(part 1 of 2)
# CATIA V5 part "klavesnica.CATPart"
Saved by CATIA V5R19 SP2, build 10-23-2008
Part number: Part1
Bounding box of the stored display mesh (mm): x -64 to 64, y -20 to 20, z 0 to 7.5
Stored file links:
  D:\Škola\Catia\Ovladac\klavesnica.CATPart
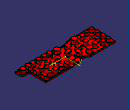
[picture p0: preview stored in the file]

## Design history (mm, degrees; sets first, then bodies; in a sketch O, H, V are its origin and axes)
Body1 (main body)
  Sketch1 on xy-plane, origin (0, 0, 0), H (1, 0, 0), V (0, 1, 0)
    line L1 (-64, -20) -> (64, -20)
    point P2 (64, -20)
    line L2 (-64, -20) -> (-64, 20)
    point P3 (-64, 20)
    line L3 (64, -20) -> (64, -7)
    line L4 (-64, 20) -> (52, 20)
    line L5 (52, 20) -> (52, -7)
    line L6 (64, -7) -> (52, -7)
    length L1 = 128
    distance P2 V = 64
    length L2 = 40
    distance P3 H = 20
    length L3 = 13
    length L4 = 116
    horizontal: L1 H, L4 H, L6 H
    vertical: L2 V, L3 V, L5 V
  Pad1: profile Sketch1, direction (0, 0, 1), length 1
  Sketch2 on end face of Pad1, origin (0, 0, 1), H (1, 0, 0), V (0, 1, 0)
    line L1 (-64, -20) -> (61, -20)
    point P2 (64, -20)
    line L2 (64, -17) -> (64, -12)
    point P3 (64, -7)
    line L3 (59, -7) -> (52, -7)
    line L4 (52, -7) -> (52, 20)
    line L5 (52, 20) -> (-64, 20)
    line L6 (-64, 20) -> (-64, -20)
    line L7 (-63, 19) -> (51, 19)
    line L8 (-63, 19) -> (-63, -19)
    line L9 (-63, -19) -> (60, -19)
    line L10 (63, -16) -> (63, -13)
    line L11 (58, -8) -> (51, -8)
    line L12 (51, -8) -> (51, 19)
    arc A1 centre (58, -13) radius 5 from (63, -13) to (58, -8) ccw
    arc A2 centre (59, -12) radius 5 from (64, -12) to (59, -7) ccw
    reference projected line E1 (64, -20) -> (64, -7) from edge [face of Pad1 from Sketch1.L3 | end face of Pad1]
    arc A3 centre (60, -16) radius 3 from (63, -16) to (60, -19) cw
    arc A4 centre (61, -17) radius 3 from (64, -17) to (61, -20) cw
    reference projected line E2 (52, -7) -> (52, 20) from edge [face of Pad1 from Sketch1.L5 | end face of Pad1]
    distance L7 L5 = 1
    distance L9 L1 = 1
    distance L8 L6 = 1
    distance L11 L3 = 1
    radius A1 = 5
    radius A2 = 5
    distance L10 E1 = 1
    radius A3 = 3
    radius A4 = 3
    distance E2 L4 = 0
    distance L4 L12 = 1
    horizontal: L1 H, L3 H, L5 H, L7 H, L9 H, L11 H
    vertical: L2 V, L4 V, L6 V, L8 V, L10 V, L12 V
    tangency: A1 L10, A1 L11, A2 L2, A2 L3, A3 L10, A3 L9, A4 L2, A4 L1
    coincidence: L2 P3, L3 P3, L2 P2
  Pad2: profile Sketch2, direction (0, 0, 1), length 1
  Sketch3 on end face of Pad2, origin (0, 0, 2), H (1, 0, 0), V (0, 1, 0)
    line L1 (-68, 9) -> (-58, 9)
    line L2 (-58, 9) -> (-58, 19)
    line L3 (-58, 19) -> (-68, 19)
    line L4 (-68, 19) -> (-68, 9)
    reference projected line E1 (52, 20) -> (-64, 20) from edge [face of Pad2 | end face of Pad2]
    length L4 = 10
    distance L3 E1 = 1
    horizontal: L1 H, L3 H
    vertical: L2 V, L4 V
  Pocket1: profile Sketch3, direction (0, 0, -1), length 1
  Sketch4 on end face of Pad2, origin (0, 0, 2), H (1, 0, 0), V (0, 1, 0)
    circle A1 centre (-64, 0) radius 2.5
    point P1 (-64, 0)
    reference projected line E1 (-64, 9) -> (-63, 9) from edge [end face of Pad2 | face of Pocket1 from Sketch3.L1]
    reference projected line E2 (-64, 20) -> (-64, -20) from edge [face of Pad2 | end face of Pad2]
    radius A1 = 2.5
    distance P1 E1 = 9
    distance P1 E2 = 0
  Pocket2: profile Sketch4, direction (0, 0, -1), length 3
  Sketch5 on face of Pocket1, origin (0, 0, 1), H (1, 0, 0), V (0, 1, 0)
    arc A1 centre (-64, 0) radius 2 from (-64, -2) to (-64, 2) ccw
    point P1 (-64, 0)
    arc A2 centre (-64, 0) radius 2.5 from (-64, -2.5) to (-64, 2.5) ccw
    line L1 (-64, -2) -> (-64, -2.5)
    line L2 (-64, 2) -> (-64, 2.5)
    radius A1 = 2
    radius A2 = 2.5
    coincidence: P1 H
    vertical: L1 V, L2 V
  Pad3: profile Sketch5, direction (0, 0, 1), length 1
  Sketch6 on face of Pad3, origin (0, 0, 2), H (1, 0, 0), V (0, 1, 0)
    line L1 (-22, -20) -> (-18.5, -16.8182)
    point P1 (-22, -20)
    point P2 (-18.5, -16.8182)
    line L2 (-22, -20) -> (-5, -20)
    point P3 (-5, -20)
    line L3 (-5, -20) -> (-8.5, -16.8182)
    point P4 (-8.5, -16.8182)
    axis line L4 (-13.5, -22) -> (-13.5, -10)
    line L5 (-8.5, -16.8182) -> (-18.5, -16.8182)
    point P7 (-5, 20)
    point P8 (-22, 20)
    line L6 (-22, 20) -> (-5, 20)
    point P9 (-8.5, 16.8182)
    line L7 (-5, 20) -> (-8.5, 16.8182)
    point P10 (-18.5, 16.8182)
    line L8 (-8.5, 16.8182) -> (-18.5, 16.8182)
    line L9 (-22, 20) -> (-18.5, 16.8182)
    length L2 = 17
    distance P3 V = 5
    distance L4 P1 = 8.5
    coincidence: L1 O
    horizontal: L2 H, L5 H
    vertical: L4 V
    symmetry: P3 P7 H, P1 P8 H, L2 L6 H, P4 P9 H, L3 L7 H, P2 P10 H, L5 L8 H, L1 L9 H
  Pocket3: profile Sketch6, direction (0, 0, -1), length 4
  Sketch7 on face of Pad2, origin (0, 20, 0), H (-1, 0, 0), V (0, 0, 1)
    reference projected line E1 (-52, 0) -> (64, 0) from edge [start face of Pad1 | face of Pad2]
    reference projected line E2 (-52, 2) -> (64, 2) from edge [face of Pad2 | face of Pad3]
    distance E1 E2 = 2 (reference)
  Sketch8 on face of Pocket1, origin (0, 0, 1), H (1, 0, 0), V (0, 1, 0)
    point P1 (-6, -20)
    line L1 (-6, -20) -> (4, -20)
    line L2 (4, -20) -> (4, -19)
    line L3 (4, -19) -> (-6, -19)
    line L4 (-6, -19) -> (-6, -20)
    point P2 (4, -20)
    point P3 (4, -19)
    point P4 (-6, -19)
    reference projected point E1 (-5, -20) from vertex [face of Pocket3 from Sketch6.L3 | face of Pad2 | face of Pad3]
    point P5 (-6, 19)
    point P6 (4, 19)
    line L5 (4, 19) -> (-6, 19)
    point P7 (-6, 20)
    line L6 (-6, 19) -> (-6, 20)
    point P8 (4, 20)
    line L7 (-6, 20) -> (4, 20)
    line L8 (4, 20) -> (4, 19)
    length L1 = 10
    distance L4 E1 = 1
    length L4 = 1
    horizontal: L1 H, L3 H
    vertical: L2 V, L4 V
    symmetry: P4 P5 H, P3 P6 H, L3 L5 H, P1 P7 H, L4 L6 H, P2 P8 H, L1 L7 H, L2 L8 H
  Pocket4: profile Sketch8, direction (0, 0, 1), length 3, mirrored extent
  Sketch9 on face of Pad3, origin (0, 0, 2), H (1, 0, 0), V (0, 1, 0)
    point P1 (-6, -19)
    line L1 (-6, -19) -> (-10, -19)
    line L2 (-10, -19) -> (-10, -21)
    line L3 (-10, -21) -> (-6, -21)
    line L4 (-6, -21) -> (-6, -19)
    point P2 (-10, -19)
    point P3 (-10, -21)
    point P4 (-6, -21)
    reference projected line E1 (-63, -19) -> (63, -19) from edge [face of Pad3 | face of Pad2 from Sketch2.L9]
    point P5 (-6, 19)
    point P6 (-6, 21)
    line L5 (-6, 21) -> (-6, 19)
    point P7 (-10, 19)
    line L6 (-6, 19) -> (-10, 19)
    point P8 (-10, 21)
    line L7 (-10, 21) -> (-6, 21)
    line L8 (-10, 19) -> (-10, 21)
    distance E1 L1 = 0
    horizontal: L1 H, L3 H
    vertical: L2 V, L4 V
    symmetry: P1 P5 H, P4 P6 H, L4 L5 H, P2 P7 H, L1 L6 H, P3 P8 H, L3 L7 H, L2 L8 H
  Pocket5: profile Sketch9, direction (0, 0, -1), length 3
  Sketch10 on face of Pocket1, origin (0, 0, 1), H (1, 0, 0), V (0, 1, 0)
    line L1 (-18.5, -16.8182) -> (-8.5, -16.8182)
    point P1 (-18.5, -16.8182)
    point P2 (-8.5, -16.8182)
    line L2 (-18.5, -16.8182) -> (-22.0601, -20.0546)
    point P3 (-22.0601, -20.0546)
    line L3 (-22.0601, -20.0546) -> (-22.0601, -20.0546)
    line L4 (-22.0601, -20.0546) -> (-22.7466, -19.3275)
    point P5 (-22.7466, -19.3275)
    line L5 (-22.7466, -19.3275) -> (-18.8863, -15.8182)
    line L6 (-18.8863, -15.8182) -> (-8.1151, -15.8182)
    point P6 (-18.8863, -15.8182)
    point P7 (-6.1, -19)
    line L7 (-6.1, -19) -> (4, -19)
    point P8 (4, -19)
    line L8 (4, -19) -> (4, -18)
    point P9 (4, -18)
    line L9 (4, -18) -> (-5.7151, -18)
    line L10 (-6.1, -19) -> (-8.5, -16.8182)
    line L11 (-5.7151, -18) -> (-8.1151, -15.8182)
    point P10 (-5.7151, -18)
    point P11 (-8.1151, -15.8182)
    point P12 (-8.1151, 15.8182)
    point P13 (-18.8863, 15.8182)
    line L12 (-18.8863, 15.8182) -> (-8.1151, 15.8182)
    point P14 (-8.5, 16.8182)
    point P15 (-18.5, 16.8182)
    line L13 (-18.5, 16.8182) -> (-8.5, 16.8182)
    point P16 (-22.0601, 20.0546)
    line L14 (-18.5, 16.8182) -> (-22.0601, 20.0546)
    point P17 (-22.7466, 19.3275)
    line L15 (-22.7466, 19.3275) -> (-18.8863, 15.8182)
    line L16 (-22.0601, 20.0546) -> (-22.7466, 19.3275)
    point P18 (-5.7151, 18)
    line L17 (-5.7151, 18) -> (-8.1151, 15.8182)
    point P19 (-6.1, 19)
    line L18 (-6.1, 19) -> (-8.5, 16.8182)
    point P20 (4, 18)
    line L19 (4, 18) -> (-5.7151, 18)
    point P21 (4, 19)
    line L20 (-6.1, 19) -> (4, 19)
    line L21 (4, 19) -> (4, 18)
    symmetry: P11 P12 H, P6 P13 H, L6 L12 H, P2 P14 H, P1 P15 H, L1 L13 H, P3 P16 H, L2 L14 H, P5 P17 H, L5 L15 H, L4 L16 H, P10 P18 H, L11 L17 H, P7 P19 H, L10 L18 H, P9 P20 H, L9 L19 H, P8 P21 H, L7 L20 H, L8 L21 H
  Sketch11 on face of Pocket1, origin (0, 0, 1), H (1, 0, 0), V (0, 1, 0)
    line L1 (4, -19) -> (4, -18)
    point P1 (4, -19)
    reference projected point E1 (4, -19) from vertex [element of Sketch10 | element of Sketch10]
    length L1 = 1
    distance P1 E1 = 0
    vertical: L1 V
  Pad4: profile Sketch10, direction (0, 0, 1), length 1
  Sketch12 on face of Pad4, origin (0, 0, 2), H (1, 0, 0), V (0, 1, 0)
    line L1 (10, -20) -> (6, -20)
    point P1 (10, -20)
    point P2 (6, -20)
    line L2 (10, -20) -> (10, -19)
    point P3 (10, -19)
    line L3 (10, -19) -> (6, -19)
    point P4 (6, -19)
    line L4 (6, -20) -> (4, -19)
    point P5 (4, -19)
    line L5 (4, -18) -> (6, -19)
    point P6 (4, -18)
    line L6 (4, -18) -> (4, -19)
    point P7 (6, 19)
    point P8 (4, 18)
    line L7 (4, 18) -> (6, 19)
    point P9 (4, 19)
    point P10 (6, 20)
    line L8 (6, 20) -> (4, 19)
    line L9 (4, 18) -> (4, 19)
    point P11 (10, 19)
    line L10 (10, 19) -> (6, 19)
    point P12 (10, 20)
    line L11 (10, 20) -> (10, 19)
    line L12 (10, 20) -> (6, 20)
    length L1 = 4
    length L2 = 1
    horizontal: L1 H, L3 H
    vertical: L2 V
    coincidence: P5 L3
    parallelism: L4 L5, L6 L2
    symmetry: P4 P7 H, P6 P8 H, L5 L7 H, P5 P9 H, P2 P10 H, L4 L8 H, L6 L9 H, P3 P11 H, L3 L10 H, P1 P12 H, L2 L11 H, L1 L12 H
  Pocket6: profile Sketch12, direction (0, 0, -1), length 1
  Sketch13 on face of Pad3, origin (0, 0, 2), H (1, 0, 0), V (0, 1, 0)
    point P1 (4, -19)
    line L1 (4, -19) -> (4, -20)
    point P2 (4, -20)
    line L2 (4, -20) -> (6, -20)
    point P3 (6, -20)
    line L3 (6, -20) -> (4, -19)
    point P4 (4, 19)
    point P5 (6, 20)
    line L4 (6, 20) -> (4, 19)
    point P6 (4, 20)
    line L5 (4, 20) -> (6, 20)
    line L6 (4, 19) -> (4, 20)
    vertical: L1 V
    horizontal: L2 H
    symmetry: P1 P4 H, P3 P5 H, L3 L4 H, P2 P6 H, L2 L5 H
  Pocket7: profile Sketch13, direction (0, 0, -1), length 3
  Sketch14 on end face of Pad1, origin (0, 0, 1), H (1, 0, 0), V (0, 1, 0)
    line L1 (64, -12) -> (64, -14.0135)
    line L2 (59, -7) -> (56, -7)
    arc A1 centre (59, -12) radius 5 from (64, -12) to (59, -7) ccw
    line L3 (64, -14.0135) -> (68, -14.0135)
    line L4 (68, -14.0135) -> (68, -6)
    line L5 (68, -6) -> (56, -6)
    line L6 (56, -6) -> (56, -7)
    radius A1 = 5
    vertical: L1 V, L4 V, L6 V
    horizontal: L2 H, L3 H, L5 H
    tangency: A1 L1, A1 L2
  Pocket8: profile Sketch14, direction (0, 0, -1), length 3
  Sketch15 on end face of Pad1, origin (0, 0, 1), H (1, 0, 0), V (0, 1, 0)
    line L1 (64, -17) -> (64, -14.8164)
    line L2 (61, -20) -> (56.8164, -20)
    arc A1 centre (61, -17) radius 3 from (61, -20) to (64, -17) ccw
    reference projected line E1 (64, -17) -> (64, -12) from edge [face of Pocket8 | face of Pad3]
    line L3 (56.8164, -20) -> (56.8164, -22)
    line L4 (56.8164, -22) -> (66, -22)
    line L5 (66, -22) -> (66, -14.8164)
    line L6 (66, -14.8164) -> (64, -14.8164)
    radius A1 = 3
    distance L1 E1 = 0
    vertical: L1 V, L3 V, L5 V
    horizontal: L2 H, L4 H, L6 H
    tangency: A1 L2, A1 L1
  Pocket9: profile Sketch15, direction (0, 0, -1), length 3
  Sketch16 on face of Pocket6, origin (0, 0, 1), H (1, 0, 0), V (0, 1, 0)
    line L1 (69.438, -27) -> (57.438, -27)
    line L2 (57.438, -27) -> (57.438, -20)
    line L3 (58.438, -19) -> (69.438, -19)
    line L4 (69.438, -19) -> (69.438, -27)
    reference projected line E1 (-64, -20) -> (61, -20) from edge [face of Pocket9 | face of Pad3]
    reference projected line E2 (64, -17) -> (64, -12) from edge [face of Pocket9 | face of Pad3]
    arc A1 centre (58.438, -20) radius 1 from (58.438, -19) to (57.438, -20) ccw
    distance L3 E1 = 1
    distance E2 L2 = 6.562
    radius A1 = 1
    horizontal: L1 H, L3 H
    vertical: L2 V, L4 V
    tangency: A1 L3, A1 L2
  Pocket10: profile Sketch16, direction (0, 0, -1), length 3, mirrored extent
  Sketch17 on face of Pocket6, origin (0, 0, 1), H (1, 0, 0), V (0, 1, 0)
    point P1 (60, -19)
    point P2 (57.438, -18)
    arc A1 centre (58.438, -20) radius 1 from (58.438, -19) to (57.438, -20) ccw
    point P4 (57.438, -20)
    line L1 (57.438, -20) -> (57.438, -19)
    arc A2 centre (58.438, -19) radius 1 from (58.438, -18) to (57.438, -19) ccw
    reference projected point E1 (60, -19) from vertex [face of Pad2 from Sketch2.A3 | face of Pocket10 from Sketch16.L3 | face of Pad3]
    line L2 (58.438, -19) -> (62.088, -19)
    line L3 (58.438, -18) -> (62.088, -18)
    line L4 (62.088, -18) -> (62.088, -19)
    reference projected arc E2 centre (58.438, -20) radius 1 from (58.438, -19) to (57.438, -20) ccw from edge [face of Pad3 | face of Pocket10 from Sketch16.A1]
    distance P4 P2 = 2
    radius A2 = 1
    distance P1 E1 = 0
    distance P4 E2 = 0
    vertical: L1 V
    coincidence: L1 P2
    tangency: A2 L1, L2 A1, L3 A2
    parallelism: L4 L1
  Pad5: profile Sketch17, direction (0, 0, 1), length 1
  Sketch18 on face of Pocket6, origin (0, 0, 1), H (1, 0, 0), V (0, 1, 0)
    circle A1 centre (-58, -13.8) radius 3
    reference projected line E1 (-64, -20) -> (61, -20) from edge [face of Pad2 | face of Pad4]
    circle A2 centre (-58, -4.6) radius 3
    circle A3 centre (-58, 4.6) radius 3
    circle A4 centre (-58, 13.8) radius 3
    reference projected line E2 (52, 20) -> (-64, 20) from edge [face of Pad2 | face of Pad4]
    reference projected line E3 (-64, 19) -> (-64, 9) from edge [face of Pad2 | face of Pocket1]
    reference projected line E4 (-64, 20) -> (-64, -20) from edge [face of Pad3 | face of Pad4]
    reference projected line E5 (-64, -2) -> (-64, -20) from edge [face of Pad3 | face of Pad3]
    reference projected line E8 (-64, -2) -> (-64, -20) from edge [face of Pad3 | face of Pad3]
    axis line L1 (-53.5, -30) -> (-53.5, 28)
    circle A5 centre (-49, 13.8) radius 3
    circle A6 centre (-49, 4.6) radius 3
    circle A7 centre (-49, -4.6) radius 3
    circle A8 centre (-49, -13.8) radius 3
    radius A1 = 3
    distance E1 A1 = 3.2
    radius A2 = 3
    radius A4 = 3
    distance A4 E2 = 3.2
    distance A4 A3 = 3.2
    radius A3 = 3
    distance A4 E3 = 3
    distance A3 E4 = 3
    distance A1 E5 = 3
    distance A2 A1 = 3.2
    distance A2 E8 = 3
    distance L1 A4 = 1.5
    vertical: L1 V
    symmetry: A4 A5 L1, A3 A6 L1, A2 A7 L1, A1 A8 L1
  Pad6: profile Sketch18, direction (0, 0, 1), length 0.5
  Draft1: PullDir end face of Pad6, Angle 33, SupportToDraft face of Pad6 from Sketch18.A1, Neutral end face of Pad6, deactivated
  Pad7: profile Sketch18, direction (0, 0, 1), length 0.5
  Draft2: PullDir end face of Pad6, Angle 30, SupportToDraft face of Pad7, Neutral face of Pad7, deactivated
  Draft3: PullDir end face of Pad6, Angle 33, SupportToDraft face of Pad7, Neutral face of Pad7, deactivated
  Draft4: PullDir end face of Pad6, Angle 33, SupportToDraft face of Pad7, Neutral face of Pad7, deactivated
  Draft5: PullDir end face of Pad6, Angle 33, SupportToDraft face of Pad7, Neutral face of Pad7, deactivated
  Draft6: PullDir end face of Pad6, Angle 33, SupportToDraft face of Pad7, Neutral face of Pad7, deactivated
  Draft7: PullDir end face of Pad6, Angle 33, SupportToDraft face of Pad7, Neutral face of Pad7, deactivated
  Sketch19 on face of Pocket6, origin (0, 0, 1), H (1, 0, 0), V (0, 1, 0)
    circle A1 centre (-39.2169, -10.5) radius 3.5
    reference projected line E1 (-63, -19) -> (60, -19) from edge [face of Pad4 | face of Pad2 from Sketch2.L9]
    reference projected circle E2 centre (-49, -13.8) radius 3.3247 from edge [face of Pad7 | face of Pocket6]
    circle A2 centre (-39.2169, 10.5) radius 3.5
    distance A1 E1 = 5
    radius A1 = 3.5
    distance A1 E2 = 3.5
    symmetry: A1 A2 H
  Pad8: profile Sketch19, direction (0, 0, 1), length 0.5, deactivated
  Draft8: PullDir end face of Pad6, Angle 33, SupportToDraft face of Pad8 from Sketch19.A1, Neutral end face of Pad8, deactivated
  Draft9: PullDir end face of Pad6, Angle 33, SupportToDraft face of Pad8, Neutral end face of Pad8, deactivated
  Sketch20 on face of Pocket6, origin (0, 0, 1), H (1, 0, 0), V (0, 1, 0)
    circle A1 centre (-27.8728, -12.5) radius 4.5
    reference projected line E1 (-64, -20) -> (61, -20) from edge [face of Pad2 | face of Pad4]
    reference projected line E2 (-18.5, -16.8182) -> (-22.0601, -20.0546) from edge [face of Pad4 | face of Pad4]
    circle A2 centre (-27.8728, 12.5) radius 4.5
    circle A3 centre (0.8728, -12.5) radius 4.5
    circle A4 centre (0.8728, 12.5) radius 4.5
    radius A1 = 4.5
    distance A1 E1 = 3
    distance E2 A1 = 5
    symmetry: A1 A2 H
  Pad9: profile Sketch20, direction (0, 0, 1), length 0.5
  Draft10: PullDir end face of Pad6, Angle 33, SupportToDraft face of Pad9, Neutral end face of Pad9, deactivated
  Draft11: PullDir end face of Pad6, Angle 33, SupportToDraft face of Pad9 from Sketch20.A1, Neutral end face of Pad9, deactivated
  Sketch21 on face of Pocket6, origin (0, 0, 1), H (1, 0, 0), V (0, 1, 0)
    circle A1 centre (-34, 0) radius 3.25
    point P1 (-34, 0)
    radius A1 = 3.25
    distance V P1 = 34
    coincidence: P1 H
  Pad10: profile Sketch21, direction (0, 0, 1), length 0.5
  Draft12: PullDir end face of Pad6, Angle 33, SupportToDraft face of Pad10 from Sketch21.A1, Neutral end face of Pad10, deactivated
  Sketch22 on start face of Pad4, origin (0, 0, 1), H (1, 0, 0), V (0, -1, 0)
    line L1 (-22, 20) -> (-26, 20)
    line L2 (-26, 20) -> (-26, 22)
    line L3 (-26, 22) -> (-22, 22)
    line L4 (-22, 22) -> (-22, 20)
    horizontal: L1 H, L3 H
    vertical: L2 V, L4 V
  Pocket11: profile Sketch22, direction (0, 0, 1), length 1.5
  Sketch23 on start face of Pad4, origin (0, 0, 1), H (1, 0, 0), V (0, -1, 0)
    line L1 (-20, -20) -> (-24, -20)
    line L2 (-24, -20) -> (-24, -22)
    line L3 (-24, -22) -> (-20, -22)
    line L4 (-20, -22) -> (-20, -20)
    horizontal: L1 H, L3 H
    vertical: L2 V, L4 V
  Pocket12: profile Sketch23, direction (0, 0, 1), length 1.5
  Draft13: PullDir end face of Pad6, Angle 33, SupportToDraft face of Pad8 from Sketch19.A2, Neutral end face of Pad8, deactivated
  Draft14: PullDir end face of Pad6, Angle 33, SupportToDraft face of Pad9 from Sketch20.A2, Neutral end face of Pad9, deactivated
  Draft15: PullDir end face of Pad6, Angle 33, SupportToDraft face of Pad9 from Sketch20.A3, Neutral end face of Pad9, deactivated
  Draft16: PullDir end face of Pad6, Angle 33, SupportToDraft face of Pad9 from Sketch20.A4, Neutral end face of Pad9
  Sketch24 on face of Pocket6, origin (0, 0, 1), H (1, 0, 0), V (0, 1, 0)
    arc A1 centre (11.8207, -16) radius 2 from (10.3658, -17.3723) to (11.8207, -18) ccw
    arc A2 centre (11.8207, -12) radius 2 from (11.8207, -10) to (10.415, -10.5773) ccw
    arc A3 centre (13.9293, -14.134) radius 5 from (9.3483, -12.1304) to (10.415, -10.5773) cw
    point P1 (9.3483, -12.1304)
    point P2 (10.415, -10.5773)
    arc A4 centre (14.0031, -13.9416) radius 5 from (10.3658, -17.3723) to (9.2628, -12.351) cw
    point P3 (10.3658, -17.3723)
    point P4 (9.2628, -12.351)
    point P5 (11.8207, -10)
    point P6 (11.8207, -18)
    point P7 (13.2265, -10.5773)
    point P8 (11.8207, -10)
    arc A5 centre (11.8207, -12) radius 2 from (11.8207, -10) to (13.2265, -10.5773) cw
    point P9 (14.2932, -12.1304)
    arc A6 centre (9.7122, -14.134) radius 5 from (14.2932, -12.1304) to (13.2265, -10.5773) ccw
    point P10 (14.3786, -12.351)
    point P11 (13.2757, -17.3723)
    arc A7 centre (9.6384, -13.9416) radius 5 from (13.2757, -17.3723) to (14.3786, -12.351) ccw
    point P12 (11.8207, -18)
    arc A8 centre (11.8207, -16) radius 2 from (13.2757, -17.3723) to (11.8207, -18) cw
    line L1 (14.3786, -12.351) -> (14.2932, -12.1304)
    line L2 (9.2628, -12.351) -> (9.3483, -12.1304)
    reference projected line E1 (-64, -20) -> (61, -20) from edge [face of Pocket9 | face of Pad5]
    reference projected line E2 (-64, -20) -> (61, -20) from edge [face of Pocket9 | face of Pad5]
    point P13 (13.2265, 10.5773)
    point P14 (14.2932, 12.1304)
    arc A9 centre (9.7122, 14.134) radius 5 from (14.2932, 12.1304) to (13.2265, 10.5773) cw
    point P15 (11.8207, 10)
    arc A10 centre (11.8207, 12) radius 2 from (11.8207, 10) to (13.2265, 10.5773) ccw
    point P16 (10.415, 10.5773)
    point P17 (11.8207, 10)
    arc A11 centre (11.8207, 12) radius 2 from (11.8207, 10) to (10.415, 10.5773) cw
    point P18 (9.3483, 12.1304)
    arc A12 centre (13.9293, 14.134) radius 5 from (9.3483, 12.1304) to (10.415, 10.5773) ccw
    point P19 (9.2628, 12.351)
    point P20 (10.3658, 17.3723)
    arc A13 centre (14.0031, 13.9416) radius 5 from (10.3658, 17.3723) to (9.2628, 12.351) ccw
    point P21 (11.8207, 18)
    arc A14 centre (11.8207, 16) radius 2 from (10.3658, 17.3723) to (11.8207, 18) cw
    point P22 (11.8207, 18)
    point P23 (13.2757, 17.3723)
    arc A15 centre (11.8207, 16) radius 2 from (13.2757, 17.3723) to (11.8207, 18) ccw
    point P24 (14.3786, 12.351)
    arc A16 centre (9.6384, 13.9416) radius 5 from (13.2757, 17.3723) to (14.3786, 12.351) cw
    line L3 (9.2628, 12.351) -> (9.3483, 12.1304)
    line L4 (14.3786, 12.351) -> (14.2932, 12.1304)
    distance A8 E1 = 2
    distance A1 E2 = 2
    tangency: A3 A2, A4 A1
    symmetry: P7 P13 H, P9 P14 H, A6 A9 H, P8 P15 H, A5 A10 H, P2 P16 H, P5 P17 H, A2 A11 H, P1 P18 H, A3 A12 H, P4 P19 H, P3 P20 H, A4 A13 H, P6 P21 H, A1 A14 H, P12 P22 H, P11 P23 H, A8 A15 H, P10 P24 H, A7 A16 H, L2 L3 H, L1 L4 H
    coincidence: P6 P12, P5 P8, P15 P17, P21 P22
  Pad11: profile Sketch24, direction (0, 0, 1), length 0.5
  Draft17: PullDir end face of Pad6, Angle 33, SupportToDraft (face of Pad11 from Sketch24.A9; face of Pad11 from Sketch24.A16; face of Pad11 from Sketch24.L4; face of Pad11 from Sketch24.L3), Neutral end face of Pad11
  Draft18: PullDir end face of Pad6, Angle 33, SupportToDraft (face of Pad11 from Sketch24.A4; face of Pad11 from Sketch24.A3; face of Pad11 from Sketch24.L2; face of Pad11 from Sketch24.L1), Neutral end face of Pad11
  Sketch25 on face of Pocket6, origin (0, 0, 1), H (1, 0, 0), V (0, 1, 0)
    circle A1 centre (12, 0) radius 3.5
    point P1 (12, 0)
    circle A2 centre (20.463, 0) radius 3.5
    point P2 (20.463, 0)
    circle A3 centre (20.4629, -13.9974) radius 3.5
    circle A4 centre (20.4629, 14.0037) radius 3.5
    reference projected arc E1 centre (9.6384, 13.9416) radius 5.3247 from (14.684, 12.2405) to (13.5119, 17.5951) ccw from edge [face of Pad11 from Sketch24.A16 | face of Pocket6]
    circle A5 centre (29.9629, -13.9974) radius 3.5
    circle A6 centre (29.963, 0) radius 3.5
    circle A7 centre (29.9629, 14.0037) radius 3.5
    circle A8 centre (39.4629, -13.9974) radius 3.5
    circle A9 centre (39.463, 0) radius 3.5
    circle A10 centre (39.4629, 14.0037) radius 3.5
    construction line L1 (47.463, 15.5) -> (47.463, 10.5)
    line L2 (49.963, 15.5) -> (49.963, 10.5)
    line L3 (44.963, 10.5) -> (44.963, 15.5)
    arc A11 centre (47.463, 10.5) radius 2.5 from (49.963, 10.5) to (44.963, 10.5) cw
    arc A12 centre (47.463, 15.5) radius 2.5 from (44.963, 15.5) to (49.963, 15.5) cw
    point P13 (49.963, 15.5)
    point P14 (49.963, 10.5)
    point P15 (44.963, 10.5)
    point P16 (44.963, 15.5)
    point P17 (44.963, -10.5)
    point P18 (49.963, -10.5)
    arc A13 centre (47.463, -10.5) radius 2.5 from (49.963, -10.5) to (44.963, -10.5) ccw
    point P20 (44.963, -15.5)
    line L4 (44.963, -10.5) -> (44.963, -15.5)
    point P21 (49.963, -15.5)
    arc A14 centre (47.463, -15.5) radius 2.5 from (44.963, -15.5) to (49.963, -15.5) ccw
    line L5 (49.963, -15.5) -> (49.963, -10.5)
    construction line L6 (47.463, -2.5) -> (47.463, 2.5)
    point P23 (47.463, -2.5)
    line L7 (44.963, -2.5) -> (44.963, 2.5)
    line L8 (49.963, 2.5) -> (49.963, -2.5)
    arc A15 centre (47.463, 2.5) radius 2.5 from (44.963, 2.5) to (49.963, 2.5) cw
    arc A16 centre (47.463, -2.5) radius 2.5 from (49.963, -2.5) to (44.963, -2.5) cw
    reference projected arc E2 centre (9.6384, -13.9416) radius 5.3247 from (13.5119, -17.5951) to (14.684, -12.2405) ccw from edge [face of Pad11 from Sketch24.A7 | face of Pocket6]
    reference projected line E3 (52, -7) -> (52, 20) from edge [face of Pad2 | face of Pad5]
    radius A1 = 3.5
    radius A2 = 3.5
    radius A3 = 3.5
    radius A4 = 3.5
    distance A4 E1 = 2
    distance A7 A4 = 2.5
    distance A6 A2 = 2.5
    distance A5 A3 = 2.5
    distance A2 A1 = 1.463
    distance A10 A7 = 2.5
    distance A9 A6 = 2.5
    distance A8 A5 = 2.5
    distance L1 L2 = 2.5
    distance L6 L7 = 2.5
    distance A15 A16 = 10
    distance A11 A15 = 3
    distance A3 E2 = 2
    distance L2 E3 = 2.037
    coincidence: P1 H, P2 H, P23 L1
    vertical: L1 V, L6 V
    tangency: A11 L2, A12 L2, A11 L3, A12 L3, A15 L7, A16 L7, A15 L8, A16 L8
    symmetry: P15 P17 H, P14 P18 H, A11 A13 H, P16 P20 H, L3 L4 H, P13 P21 H, A12 A14 H, L2 L5 H
    fix: A1
  Pad12: profile Sketch25, direction (0, 0, 1), length 0.5
  Draft19: PullDir end face of Pad6, Angle 33, SupportToDraft (face of Pad12 from Sketch25.A1; face of Pad12 from Sketch25.A2; face of Pad12 from Sketch25.A4; face of Pad12 from Sketch25.A3; face of Pad12 from Sketch25.A7; face of Pad12 from Sketch25.A6; face of Pad12 from Sketch25.A5; face of Pad12 from Sketch25.A10; face of Pad12 from Sketch25.A9; face of Pad12 from Sketch25.A8), Neutral (end face of Pad12; end face of Pad12; end face of Pad12; end face of Pad12; end face of Pad12; end face of Pad12; end face of Pad12; end face of Pad12; end face of Pad12; end face of Pad12)
  Draft20: PullDir end face of Pad6, Angle 33, SupportToDraft (face of Pad12 from Sketch25.A16; face of Pad12 from Sketch25.A11; face of Pad12 from Sketch25.L4), Neutral (end face of Pad12; end face of Pad12; end face of Pad12)
  Sketch26 on face of Pocket6, origin (0, 0, 1), H (1, 0, 0), V (0, 1, 0)
    arc A1 centre (56.6247, -13) radius 4 from (60.5344, -12.1548) to (60.5344, -13.8452) ccw
    arc A2 centre (60, -13) radius 1 from (60.5344, -13.8452) to (60.5344, -12.1548) ccw
  Pad13: profile Sketch26, direction (0, 0, 1), length 0.5
  Draft21: PullDir end face of Pad6, Angle 33, SupportToDraft (face of Pad13 from Sketch26.A1; face of Pad13 from Sketch26.A2), Neutral end face of Pad13
  Sketch27 on face of Pocket6, origin (0, 0, 1), H (1, 0, 0), V (0, 1, 0)
    construction line L1 (-13.5, -10.5) -> (-13.5, -7.5)
    line L2 (-17, -10.5) -> (-17, -7.5)
    line L3 (-10, -7.5) -> (-10, -10.5)
    arc A1 centre (-13.5, -7.5) radius 3.5 from (-17, -7.5) to (-10, -7.5) cw
    arc A2 centre (-13.5, -10.5) radius 3.5 from (-10, -10.5) to (-17, -10.5) cw
    point P3 (-17, -10.5)
    point P4 (-17, -7.5)
    point P5 (-10, -7.5)
    point P6 (-10, -10.5)
    point P7 (-10, 7.5)
    point P8 (-17, 7.5)
    arc A3 centre (-13.5, 7.5) radius 3.5 from (-17, 7.5) to (-10, 7.5) ccw
    point P10 (-10, 10.5)
    line L4 (-10, 7.5) -> (-10, 10.5)
    point P11 (-17, 10.5)
    arc A4 centre (-13.5, 10.5) radius 3.5 from (-10, 10.5) to (-17, 10.5) ccw
    line L5 (-17, 10.5) -> (-17, 7.5)
    construction line L6 (-21, 0) -> (-24, 0)
    point P13 (-21, 0)
    line L7 (-21, -3.5) -> (-24, -3.5)
    line L8 (-24, 3.5) -> (-21, 3.5)
    arc A5 centre (-24, 0) radius 3.5 from (-24, -3.5) to (-24, 3.5) cw
    arc A6 centre (-21, 0) radius 3.5 from (-21, 3.5) to (-21, -3.5) cw
    point P15 (-21, -3.5)
    point P16 (-24, -3.5)
    point P17 (-24, 3.5)
    point P18 (-21, 3.5)
    axis line L9 (-13.5, 7.5) -> (-13.5, 3.5)
    point P19 (-13.5, 3.5)
    point P20 (-6, -3.5)
    point P21 (-6, 3.5)
    arc A7 centre (-6, 0) radius 3.5 from (-6, 3.5) to (-6, -3.5) ccw
    point P23 (-3, 3.5)
    line L10 (-3, 3.5) -> (-6, 3.5)
    point P24 (-3, -3.5)
    arc A8 centre (-3, 0) radius 3.5 from (-3, -3.5) to (-3, 3.5) ccw
    line L11 (-6, -3.5) -> (-3, -3.5)
    distance A3 A4 = 10
    distance L6 L7 = 3.5
    distance A5 A6 = 10
    vertical: L1 V, L9 V
    tangency: A1 L2, A2 L2, A1 L3, A2 L3, A5 L7, A6 L7, A5 L8, A6 L8
    symmetry: P5 P7 H, P4 P8 H, A1 A3 H, P6 P10 H, L3 L4 H, P3 P11 H, A2 A4 H, L2 L5 H, P15 P20 L9, P18 P21 L9, A6 A7 L9, P17 P23 L9, L8 L10 L9, P16 P24 L9, A5 A8 L9, L7 L11 L9
    coincidence: P13 H, P19 L8
    horizontal: L6 H
  Pad14: profile Sketch27, direction (0, 0, 1), length 0.5
  Draft22: PullDir end face of Pad6, Angle 33, SupportToDraft (face of Pad14 from Sketch27.L7; face of Pad14 from Sketch27.A5), Neutral end face of Pad14
  Draft23: PullDir end face of Pad6, Angle 33, SupportToDraft (face of Pad14 from Sketch27.A3; face of Pad14 from Sketch27.A7; face of Pad14 from Sketch27.A1), Neutral (end face of Pad14; end face of Pad14; end face of Pad14)
  Sketch28 on face of Pad7, origin (0, 0, 1.5), H (1, 0, 0), V (0, 1, 0)
    circle A1 centre (-58, -13.8) radius 3
    reference projected circle E1 centre (-58, -13.8) radius 3 from edge [face of Pad6 from Sketch18.A1 | face of Pad7]
    tangency: A1 E1
  Pad15: profile Sketch28, direction (0, 0, 1), length 5, deactivated
  Sketch29 on end face of Pad8, origin (0, 0, 1.5), H (1, 0, 0), V (0, 1, 0)
    circle A1 centre (-39.2169, -10.5) radius 3.5
    circle A2 centre (-39.2169, 10.5) radius 3.5
    reference projected circle E1 centre (-39.2169, -10.5) radius 3.5 from edge [face of Pad8 from Sketch19.A1 | end face of Pad8]
    reference projected circle E2 centre (-39.2169, 10.5) radius 3.5 from edge [face of Pad8 from Sketch19.A2 | end face of Pad8]
    radius A1 = 3.5
    radius A2 = 3.5
    tangency: A1 E1, A2 E2
  Pad16: profile Sketch29, direction (0, 0, 1), length 6, deactivated
  Sketch30 on end face of Pad10, origin (0, 0, 1.5), H (1, 0, 0), V (0, 1, 0)
    reference projected circle E1 centre (-34, 0) radius 3.25 from edge [face of Pad10 from Sketch21.A1 | end face of Pad10]
    circle A1 centre (-34, 0) radius 3.25
    radius E1 = 3.25 (reference)
    radius A1 = 3.25
  Pad17: profile Sketch30, direction (0, 0, 1), length 6, deactivated
  Sketch31 on end face of Pad9, origin (0, 0, 1.5), H (1, 0, 0), V (0, 1, 0)
    reference projected circle E1 centre (-27.8728, -12.5) radius 4.5 from edge [face of Pad9 from Sketch20.A1 | end face of Pad9]
    circle A1 centre (-27.8728, -12.5) radius 4.5
    circle A2 centre (-27.8728, 12.5) radius 4.5
    reference projected circle E2 centre (-27.8728, -12.5) radius 4.5 from edge [face of Pad9 from Sketch20.A1 | end face of Pad9]
    reference projected circle E3 centre (-27.8728, 12.5) radius 4.5 from edge [face of Pad9 from Sketch20.A2 | end face of Pad9]
    radius E1 = 4.5 (reference)
    radius A2 = 4.5
    radius A1 = 4.5
    radius A2 = 4.5 (reference)
    tangency: A1 E2, A2 E3
  Pad18: profile Sketch31, direction (0, 0, 1), length 6, deactivated
  Sketch32 on end face of Pad14, origin (0, 0, 1.5), H (1, 0, 0), V (0, 1, 0)
    line L1 (-1.6, 0) -> (-1.6, 0)
    line L2 (-2.5, 0) -> (-2.5, 0)
    construction line L3 (-25.4, 0) -> (-21, 0)
    line L4 (-26.0682, 1.9909) -> (-22.1136, 3.3181)
    line L5 (-22.1136, -3.3181) -> (-26.0682, -1.9909)
    arc A1 centre (-21, 0) radius 3.5 from (-22.1136, 3.3181) to (-22.1136, -3.3181) cw
    arc A2 centre (-25.4, 0) radius 2.1 from (-26.0682, -1.9909) to (-26.0682, 1.9909) cw
    reference projected arc E1 centre (-21, 0) radius 3.5 from (-21, -3.5) to (-21, 3.5) ccw from edge [face of Pad14 from Sketch27.A6 | end face of Pad14]
    reference projected arc E2 centre (-21, 0) radius 3.5 from (-21, -3.5) to (-21, 3.5) ccw from edge [face of Pad14 from Sketch27.A6 | end face of Pad14]
    construction line L6 (-13.5, -7.5) -> (-13.5, -11.9)
    line L7 (-10.1819, -8.6136) -> (-11.5091, -12.5682)
    line L8 (-15.4909, -12.5682) -> (-16.8181, -8.6136)
    arc A3 centre (-13.5, -11.9) radius 2.1 from (-11.5091, -12.5682) to (-15.4909, -12.5682) cw
    arc A4 centre (-13.5, -7.5) radius 3.5 from (-16.8181, -8.6136) to (-10.1819, -8.6136) cw
    point P13 (-10.1819, -8.6136)
    point P14 (-11.5091, -12.5682)
    point P15 (-15.4909, -12.5682)
    point P16 (-16.8181, -8.6136)
    reference projected arc E3 centre (-13.5, -10.5) radius 3.5 from (-17, -10.5) to (-10, -10.5) ccw from edge [face of Pad14 from Sketch27.A2 | end face of Pad14]
    point P17 (-10.1819, 8.6136)
    point P18 (-16.8181, 8.6136)
    arc A5 centre (-13.5, 7.5) radius 3.5 from (-16.8181, 8.6136) to (-10.1819, 8.6136) ccw
    point P20 (-11.5091, 12.5682)
    line L9 (-10.1819, 8.6136) -> (-11.5091, 12.5682)
    point P21 (-15.4909, 12.5682)
    arc A6 centre (-13.5, 11.9) radius 2.1 from (-11.5091, 12.5682) to (-15.4909, 12.5682) ccw
    line L10 (-15.4909, 12.5682) -> (-16.8181, 8.6136)
    construction line L11 (-6, 0) -> (-1.6, 0)
    point P23 (-6, 0)
    line L12 (-4.8864, 3.3181) -> (-0.9318, 1.9909)
    line L13 (-0.9318, -1.9909) -> (-4.8864, -3.3181)
    arc A7 centre (-1.6, 0) radius 2.1 from (-0.9318, 1.9909) to (-0.9318, -1.9909) cw
    arc A8 centre (-6, 0) radius 3.5 from (-4.8864, -3.3181) to (-4.8864, 3.3181) cw
    reference projected arc E4 centre (-3, 0) radius 3.5 from (-3, -3.5) to (-3, 3.5) ccw from edge [face of Pad14 from Sketch27.A8 | end face of Pad14]
    reference projected arc E5 centre (-13.5, -7.5) radius 3.5 from (-10, -7.5) to (-17, -7.5) ccw from edge [face of Pad14 from Sketch27.A1 | end face of Pad14]
    distance A1 A2 = 10
    radius E2 = 3.5 (reference)
    distance A4 A3 = 10
    radius A7 = 2.1
    radius A8 = 3.5
    distance A7 A8 = 10
    radius A4 = 3.5
    radius A3 = 2.1
    radius A1 = 3.5
    radius A2 = 2.1
    horizontal: L3 H, L11 H
    tangency: A1 L4, A2 L4, A1 L5, A2 L5, A1 E1, A3 L7, A4 L7, A3 L8, A4 L8, A3 E3, A7 L12, A8 L12, A7 L13, A8 L13, A7 E4, A4 E5
    vertical: L6 V
    symmetry: P13 P17 H, P16 P18 H, A4 A5 H, P14 P20 H, L7 L9 H, P15 P21 H, A3 A6 H, L8 L10 H
    coincidence: P23 H
  Pad19: profile Sketch32, direction (0, 0, 1), length 5
  Sketch33 on end face of Pad9, origin (0, 0, 1.5), H (1, 0, 0), V (0, 1, 0)
    circle A1 centre (0.8728, -12.5) radius 4.5
    reference projected circle E1 centre (0.8728, -12.5) radius 4.5 from edge [face of Pad9 from Sketch20.A3 | end face of Pad9]
    circle A2 centre (0.8728, 12.5) radius 4.5
    reference projected circle E2 centre (0.8728, 12.5) radius 4.5 from edge [face of Pad9 from Sketch20.A4 | end face of Pad9]
    radius A1 = 4.5
    radius A2 = 4.5
    tangency: A1 E1, A2 E2
  Pad20: profile Sketch33, direction (0, 0, 1), length 5, deactivated
  Sketch34 on end face of Pad12, origin (0, 0, 1.5), H (1, 0, 0), V (0, 1, 0)
    reference projected circle E1 centre (12, 0) radius 3.5 from edge [face of Pad12 from Sketch25.A1 | end face of Pad12]
    reference projected circle E2 centre (20.463, 0) radius 3.5 from edge [face of Pad12 from Sketch25.A2 | end face of Pad12]
    circle A1 centre (12, 0) radius 3.5
    circle A2 centre (20.463, 0) radius 3.5
    point P2 (20.463, 0)
    circle A3 centre (20.4629, -13.9974) radius 3.5
    circle A4 centre (30, 14) radius 3.5
    circle A5 centre (39.4629, 14.0037) radius 3.5
    circle A6 centre (39.463, 0) radius 3.5
    circle A7 centre (39.4629, -13.9974) radius 3.5
    reference projected circle E3 centre (20.4629, -13.9974) radius 3.5 from edge [face of Pad12 from Sketch25.A3 | end face of Pad12]
    reference projected circle E4 centre (39.4629, -13.9974) radius 3.5 from edge [face of Pad12 from Sketch25.A8 | end face of Pad12]
    reference projected circle E5 centre (39.463, 0) radius 3.5 from edge [face of Pad12 from Sketch25.A9 | end face of Pad12]
    reference projected circle E6 centre (20.463, 0) radius 3.5 from edge [face of Pad12 from Sketch25.A2 | end face of Pad12]
    reference projected circle E7 centre (39.4629, 14.0037) radius 3.5 from edge [face of Pad12 from Sketch25.A10 | end face of Pad12]
    circle A8 centre (29.963, 0) radius 3.5
    reference projected circle E8 centre (29.963, 0) radius 3.5 from edge [face of Pad12 from Sketch25.A6 | end face of Pad12]
    circle A9 centre (29.9629, -13.9974) radius 3.5
    reference projected circle E9 centre (29.9629, -13.9974) radius 3.5 from edge [face of Pad12 from Sketch25.A5 | end face of Pad12]
    radius E1 = 3.5 (reference)
    radius E2 = 3.5 (reference)
    radius A1 = 3.5
    radius A2 = 3.5
    radius A3 = 3.5
    radius A7 = 3.5
    radius A6 = 3.5
    radius A5 = 3.5
    radius A4 = 3.5
    radius A8 = 3.5
    coincidence: P2 H
    tangency: A3 E3, A7 E4, A6 E5, A2 E6, A5 E7, A8 E8, A9 E9
  Pad21: profile Sketch34, direction (0, 0, 1), length 5
  Sketch35 on end face of Pad12, origin (0, 0, 1.5), H (1, 0, 0), V (0, 1, 0)
    circle A1 centre (20.4629, 14.0037) radius 3.5
    reference projected circle E1 centre (20.4629, 14.0037) radius 3.5 from edge [face of Pad12 from Sketch25.A4 | end face of Pad12]
    radius A1 = 3.5
    tangency: A1 E1
  Pad22: profile Sketch35, direction (0, 0, 1), length 5
  Sketch36 on end face of Pad13, origin (0, 0, 1.5), H (1, 0, 0), V (0, 1, 0)
    arc A1 centre (56.6247, -13) radius 4 from (60.5344, -12.1548) to (60.5344, -13.8452) ccw
    reference projected arc E1 centre (56.6247, -13) radius 4 from (60.5344, -12.1548) to (60.5344, -13.8452) ccw from edge [face of Pad13 from Sketch26.A1 | end face of Pad13]
    arc A2 centre (60, -13) radius 1 from (60.5344, -13.8452) to (60.5344, -12.1548) ccw
    reference projected arc E2 centre (60, -13) radius 1 from (60.5344, -13.8452) to (60.5344, -12.1548) ccw from edge [face of Pad13 from Sketch26.A2 | end face of Pad13]
    tangency: A1 E1, A2 E2
  Pad23: profile Sketch36, direction (0, 0, 1), length 5
  Sketch37 on end face of Pad12, origin (0, 0, 1.5), H (1, 0, 0), V (0, 1, 0)
    construction line L1 (47.463, -10.5) -> (47.463, -15.5)
    line L2 (49.963, -10.5) -> (49.963, -15.5)
    line L3 (44.963, -15.5) -> (44.963, -10.5)
    arc A1 centre (47.463, -15.5) radius 2.5 from (49.963, -15.5) to (44.963, -15.5) cw
    arc A2 centre (47.463, -10.5) radius 2.5 from (44.963, -10.5) to (49.963, -10.5) cw
    reference projected arc E1 centre (47.463, -15.5) radius 2.5 from (44.963, -15.5) to (49.963, -15.5) ccw from edge [face of Pad12 from Sketch25.A14 | end face of Pad12]
    distance L1 L2 = 2.5
    distance A2 A1 = 10
    vertical: L1 V
    tangency: A1 L2, A2 L2, A1 L3, A2 L3, A1 E1
  Pad24: profile Sketch37, direction (0, 0, 1), length 5
  Sketch38 on end face of Pad12, origin (0, 0, 1.5), H (1, 0, 0), V (0, 1, 0)
    construction line L1 (47.463, 2.5) -> (47.463, -2.5)
    line L2 (49.963, 2.5) -> (49.963, -2.5)
    line L3 (44.963, -2.5) -> (44.963, 2.5)
    arc A1 centre (47.463, -2.5) radius 2.5 from (49.963, -2.5) to (44.963, -2.5) cw
    arc A2 centre (47.463, 2.5) radius 2.5 from (44.963, 2.5) to (49.963, 2.5) cw
    reference projected arc E1 centre (47.463, 2.5) radius 2.5 from (49.963, 2.5) to (44.963, 2.5) ccw from edge [face of Pad12 from Sketch25.A15 | end face of Pad12]
    reference projected arc E2 centre (47.463, 2.5) radius 2.5 from (49.963, 2.5) to (44.963, 2.5) ccw from edge [face of Pad12 from Sketch25.A15 | end face of Pad12]
    radius E1 = 2.5 (reference)
    vertical: L1 V
    tangency: A1 L2, A2 L2, A1 L3, A2 L3, A2 E2
  Pad25: profile Sketch38, direction (0, 0, 1), length 5
  Sketch39 on end face of Pad12, origin (0, 0, 1.5), H (1, 0, 0), V (0, 1, 0)
    construction line L1 (47.463, 15.5) -> (47.463, 10.5)
    line L2 (49.963, 15.5) -> (49.963, 10.5)
    line L3 (44.963, 10.5) -> (44.963, 15.5)
    arc A1 centre (47.463, 10.5) radius 2.5 from (49.963, 10.5) to (44.963, 10.5) cw
    arc A2 centre (47.463, 15.5) radius 2.5 from (44.963, 15.5) to (49.963, 15.5) cw
    reference projected arc E1 centre (47.463, 10.5) radius 2.5 from (44.963, 10.5) to (49.963, 10.5) ccw from edge [face of Pad12 from Sketch25.A11 | end face of Pad12]
    vertical: L1 V
    tangency: A1 L2, A2 L2, A1 L3, A2 L3, A1 E1
  Pad26: profile Sketch39, direction (0, 0, 1), length 5
  Sketch40 on end face of Pad11, origin (0, 0, 1.5), H (1, 0, 0), V (0, 1, 0)
    construction line L1 (12, -12) -> (12, -16)
  Sketch41 on end face of Pad11, origin (0, 0, 1.5), H (1, 0, 0), V (0, 1, 0)
    point P1 (14.3786, -12.351)
    point P2 (13.2757, -17.3723)
    arc A1 centre (9.6384, -13.9416) radius 5 from (13.2757, -17.3723) to (14.3786, -12.351) ccw
    point P3 (13.2265, -10.5773)
    point P4 (14.2932, -12.1304)
    arc A2 centre (9.7122, -14.134) radius 5 from (14.2932, -12.1304) to (13.2265, -10.5773) ccw
    point P5 (9.2628, -12.351)
    point P6 (10.3658, -17.3723)
    arc A3 centre (14.0031, -13.9416) radius 5 from (10.3658, -17.3723) to (9.2628, -12.351) cw
    point P7 (10.415, -10.5773)
    point P8 (9.3483, -12.1304)
    arc A4 centre (13.9293, -14.134) radius 5 from (9.3483, -12.1304) to (10.415, -10.5773) cw
    point P9 (11.8207, -10)
    arc A5 centre (11.8207, -12) radius 2 from (11.8207, -10) to (10.415, -10.5773) ccw
    point P10 (11.8207, -10)
    arc A6 centre (11.8207, -12) radius 2 from (11.8207, -10) to (13.2265, -10.5773) cw
    point P11 (11.8207, -18)
    arc A7 centre (11.8207, -16) radius 2 from (10.3658, -17.3723) to (11.8207, -18) ccw
    point P12 (11.8207, -18)
    arc A8 centre (11.8207, -16) radius 2 from (13.2757, -17.3723) to (11.8207, -18) cw
    line L1 (9.2628, -12.351) -> (9.3483, -12.1304)
    line L2 (14.3786, -12.351) -> (14.2932, -12.1304)
    point P13 (10.415, 10.5773)
    point P14 (11.8207, 10)
    arc A9 centre (11.8207, 12) radius 2 from (11.8207, 10) to (10.415, 10.5773) cw
    point P15 (13.2265, 10.5773)
    point P16 (11.8207, 10)
    arc A10 centre (11.8207, 12) radius 2 from (11.8207, 10) to (13.2265, 10.5773) ccw
    point P17 (14.2932, 12.1304)
    arc A11 centre (9.7122, 14.134) radius 5 from (14.2932, 12.1304) to (13.2265, 10.5773) cw
    point P18 (9.3483, 12.1304)
    arc A12 centre (13.9293, 14.134) radius 5 from (9.3483, 12.1304) to (10.415, 10.5773) ccw
    point P19 (9.2628, 12.351)
    point P20 (10.3658, 17.3723)
    arc A13 centre (14.0031, 13.9416) radius 5 from (10.3658, 17.3723) to (9.2628, 12.351) ccw
    line L3 (9.2628, 12.351) -> (9.3483, 12.1304)
    point P21 (14.3786, 12.351)
    point P22 (13.2757, 17.3723)
    arc A14 centre (9.6384, 13.9416) radius 5 from (13.2757, 17.3723) to (14.3786, 12.351) cw
    line L4 (14.3786, 12.351) -> (14.2932, 12.1304)
    point P23 (11.8207, 18)
    arc A15 centre (11.8207, 16) radius 2 from (13.2757, 17.3723) to (11.8207, 18) ccw
    point P24 (11.8207, 18)
    arc A16 centre (11.8207, 16) radius 2 from (10.3658, 17.3723) to (11.8207, 18) cw
    symmetry: P7 P13 H, P9 P14 H, A5 A9 H, P3 P15 H, P10 P16 H, A6 A10 H, P4 P17 H, A2 A11 H, P8 P18 H, A4 A12 H, P5 P19 H, P6 P20 H, A3 A13 H, L1 L3 H, P1 P21 H, P2 P22 H, A1 A14 H, L2 L4 H, P12 P23 H, A8 A15 H, P11 P24 H, A7 A16 H
    coincidence: P9 P10, P11 P12, P14 P16, P23 P24
  Pad27: profile Sketch41, direction (0, 0, 1), length 5
  Fillet1: radius 0.5, on edge [face of Pad15 from Sketch28.A1 | end face of Pad15], deactivated
  Fillet2: radius 0.5, on end face of Pad16 (x2); end face of Pad17; edge [face of Pad18 from Sketch31.A2 | end face of Pad18]; end face of Pad19 (x4); end face of Pad18; end face of Pad20; edge [face of Pad20 from Sketch33.A2 | end face of Pad20]; end face of Pad27 (x2); end face of Pad21 (x9); end face of Pad22; end face of Pad26; end face of Pad25; end face of Pad24; end face of Pad23, deactivated
  Sketch42 on start face of Pad1, origin (0, 0, 0), H (1, 0, 0), V (0, -1, 0)
    circle A1 centre (-58, -13.8) radius 3
  Pocket13: profile Sketch42, direction (0, 0, 1), length 1, opposite side up to start face of Pad1
  Draft24: PullDir end face of Pocket13, Angle 33, SupportToDraft face of Pocket13 from Sketch42.A1, Neutral end face of Pocket13
  Fillet3: radius 0.5, on edge [face of Pocket13 from Sketch42.A1 | end face of Pocket13]
  Fillet4: radius 0.5, on edge [face of Pocket13 from Sketch42.A1 | start face of Pad1]
  Sketch43 on start face of Pad1, origin (0, 0, 0), H (1, 0, 0), V (0, -1, 0)
    circle A1 centre (-49, -13.8) radius 3
  Pocket14: profile Sketch43, direction (0, 0, 1), length 1, opposite side up to start face of Pad1
  Draft25: PullDir end face of Pocket14, Angle 33, SupportToDraft face of Pocket14 from Sketch43.A1, Neutral end face of Pocket14
  Fillet5: radius 0.5, on edge [face of Pocket14 from Sketch43.A1 | end face of Pocket14]
  Fillet6: radius 0.5, on edge [face of Pocket14 from Sketch43.A1 | start face of Pad1]
  Sketch44 on start face of Pad1, origin (0, 0, 0), H (1, 0, 0), V (0, -1, 0)
    circle A1 centre (-49, 13.8) radius 3
    circle A2 centre (-58, 13.8) radius 3
  Pocket15: profile Sketch44, direction (0, 0, 1), length 1, opposite side up to start face of Pad1
  Draft26: PullDir end face of Pocket15, Angle 33, SupportToDraft (face of Pocket15 from Sketch44.A1; face of Pocket15 from Sketch44.A2), Neutral end face of Pocket15
  Fillet7: radius 0.5, on edge [end face of Pocket15 | face of Pocket15 from Sketch44.A1]; edge [end face of Pocket15 | face of Pocket15 from Sketch44.A2]
  Fillet8: radius 0.5, on edge [face of Pocket15 from Sketch44.A1 | start face of Pad1]; edge [face of Pocket15 from Sketch44.A2 | start face of Pad1]
  Sketch45 on start face of Pad1, origin (0, 0, 0), H (1, 0, 0), V (0, -1, 0)
    circle A1 centre (-49, 4.6) radius 3
    circle A2 centre (-58, 4.6) radius 3
    circle A3 centre (-58, -4.6) radius 3
    circle A4 centre (-49, -4.6) radius 3
  Pocket16: profile Sketch45, direction (0, 0, 1), length 1, opposite side up to start face of Pad1
  Draft27: PullDir end face of Pocket16, Angle 33, SupportToDraft (face of Pocket16 from Sketch45.A1; face of Pocket16 from Sketch45.A2; face of Pocket16 from Sketch45.A3; face of Pocket16 from Sketch45.A4), Neutral end face of Pocket16
  Fillet9: radius 0.5, on edge [end face of Pocket16 | face of Pocket16 from Sketch45.A1]; edge [end face of Pocket16 | face of Pocket16 from Sketch45.A2]; edge [end face of Pocket16 | face of Pocket16 from Sketch45.A3]; edge [end face of Pocket16 | face of Pocket16 from Sketch45.A4]
  Fillet10: radius 0.5, on edge [face of Pocket16 from Sketch45.A1 | start face of Pad1]; edge [face of Pocket16 from Sketch45.A2 | start face of Pad1]; edge [face of Pocket16 from Sketch45.A3 | start face of Pad1]; edge [face of Pocket16 from Sketch45.A4 | start face of Pad1]
  Sketch46 on start face of Pad1, origin (0, 0, 0), H (1, 0, 0), V (0, -1, 0)
    circle A1 centre (-39.2169, -10.5) radius 3.5
    circle A2 centre (-39.2169, 10.5) radius 3.5
  Pocket17: profile Sketch46, direction (0, 0, 1), length 1, opposite side up to start face of Pad1
  Draft28: PullDir end face of Pocket17, Angle 33, SupportToDraft (face of Pocket17 from Sketch46.A1; face of Pocket17 from Sketch46.A2), Neutral end face of Pocket17
  Fillet11: radius 0.5, on edge [end face of Pocket17 | face of Pocket17 from Sketch46.A1]; edge [end face of Pocket17 | face of Pocket17 from Sketch46.A2]
  Fillet12: radius 0.5, on edge [face of Pocket17 from Sketch46.A1 | start face of Pad1]; edge [face of Pocket17 from Sketch46.A2 | start face of Pad1]
  Sketch47 on start face of Pad1, origin (0, 0, 0), H (1, 0, 0), V (0, -1, 0)
    circle A1 centre (-34, 0) radius 3.25
  Pocket18: profile Sketch47, direction (0, 0, 1), length 1, opposite side up to start face of Pad1
  Draft29: PullDir end face of Pocket18, Angle 33, SupportToDraft face of Pocket18 from Sketch47.A1, Neutral end face of Pocket18
  Fillet13: radius 0.5, on edge [face of Pocket18 from Sketch47.A1 | end face of Pocket18]
  Fillet14: radius 0.5, on edge [face of Pocket18 from Sketch47.A1 | start face of Pad1]
  Sketch48 on start face of Pad1, origin (0, 0, 0), H (1, 0, 0), V (0, -1, 0)
    circle A1 centre (20.4629, -13.9974) radius 3.5
    circle A2 centre (29.9629, -13.9974) radius 3.5
    circle A3 centre (39.4629, -13.9974) radius 3.5
    arc A4 centre (47.463, -15.5) radius 2.5 from (44.963, -15.5) to (49.963, -15.5) ccw
    line L1 (49.963, -15.5) -> (49.963, -10.5)
    line L2 (44.963, -10.5) -> (44.963, -15.5)
    arc A5 centre (47.463, -10.5) radius 2.5 from (49.963, -10.5) to (44.963, -10.5) ccw
    arc A6 centre (47.463, -2.5) radius 2.5 from (49.963, -2.5) to (44.963, -2.5) cw
    line L3 (44.963, -2.5) -> (44.963, 2.5)
    arc A7 centre (47.463, 2.5) radius 2.5 from (44.963, 2.5) to (49.963, 2.5) cw
    line L4 (49.963, 2.5) -> (49.963, -2.5)
    arc A8 centre (47.463, 10.5) radius 2.5 from (49.963, 10.5) to (44.963, 10.5) cw
    line L5 (44.963, 10.5) -> (44.963, 15.5)
    arc A9 centre (47.463, 15.5) radius 2.5 from (44.963, 15.5) to (49.963, 15.5) cw
    line L6 (49.963, 15.5) -> (49.963, 10.5)
    circle A10 centre (39.4629, 14.0037) radius 3.5
    circle A11 centre (39.463, 0) radius 3.5
    circle A12 centre (29.963, 0) radius 3.5
    circle A13 centre (20.463, 0) radius 3.5
  Pocket19: profile Sketch48, direction (0, 0, 1), length 1, opposite side up to start face of Pad1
